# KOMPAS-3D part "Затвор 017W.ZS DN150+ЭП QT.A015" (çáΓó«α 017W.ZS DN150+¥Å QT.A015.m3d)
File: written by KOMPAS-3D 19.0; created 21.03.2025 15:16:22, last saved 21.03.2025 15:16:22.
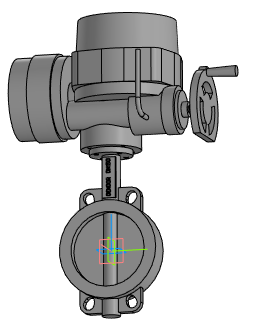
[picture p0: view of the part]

Document properties: Полное имя файла: Затвор 017W.ZS DN150+ЭП QT.A015.a3d

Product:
- Part/product: Затвор 017W.ZS DN150+ЭП QT.A015
    Масса: 99.511

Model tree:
1. Операция без истории:1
